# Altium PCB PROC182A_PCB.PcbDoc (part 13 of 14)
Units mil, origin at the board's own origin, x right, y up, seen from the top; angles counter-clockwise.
Board outline 3168.31 x 3700.79 mil, 8 copper layers (Top Layer, L2_GND1, L3_SIG1, L4_PWR1, L5_PWR2, L6_SIG2, L7_GND2, Bottom Layer), stack 58.1 mil thick; 580 components, 391 nets, 8314 pads, 4370 vias.
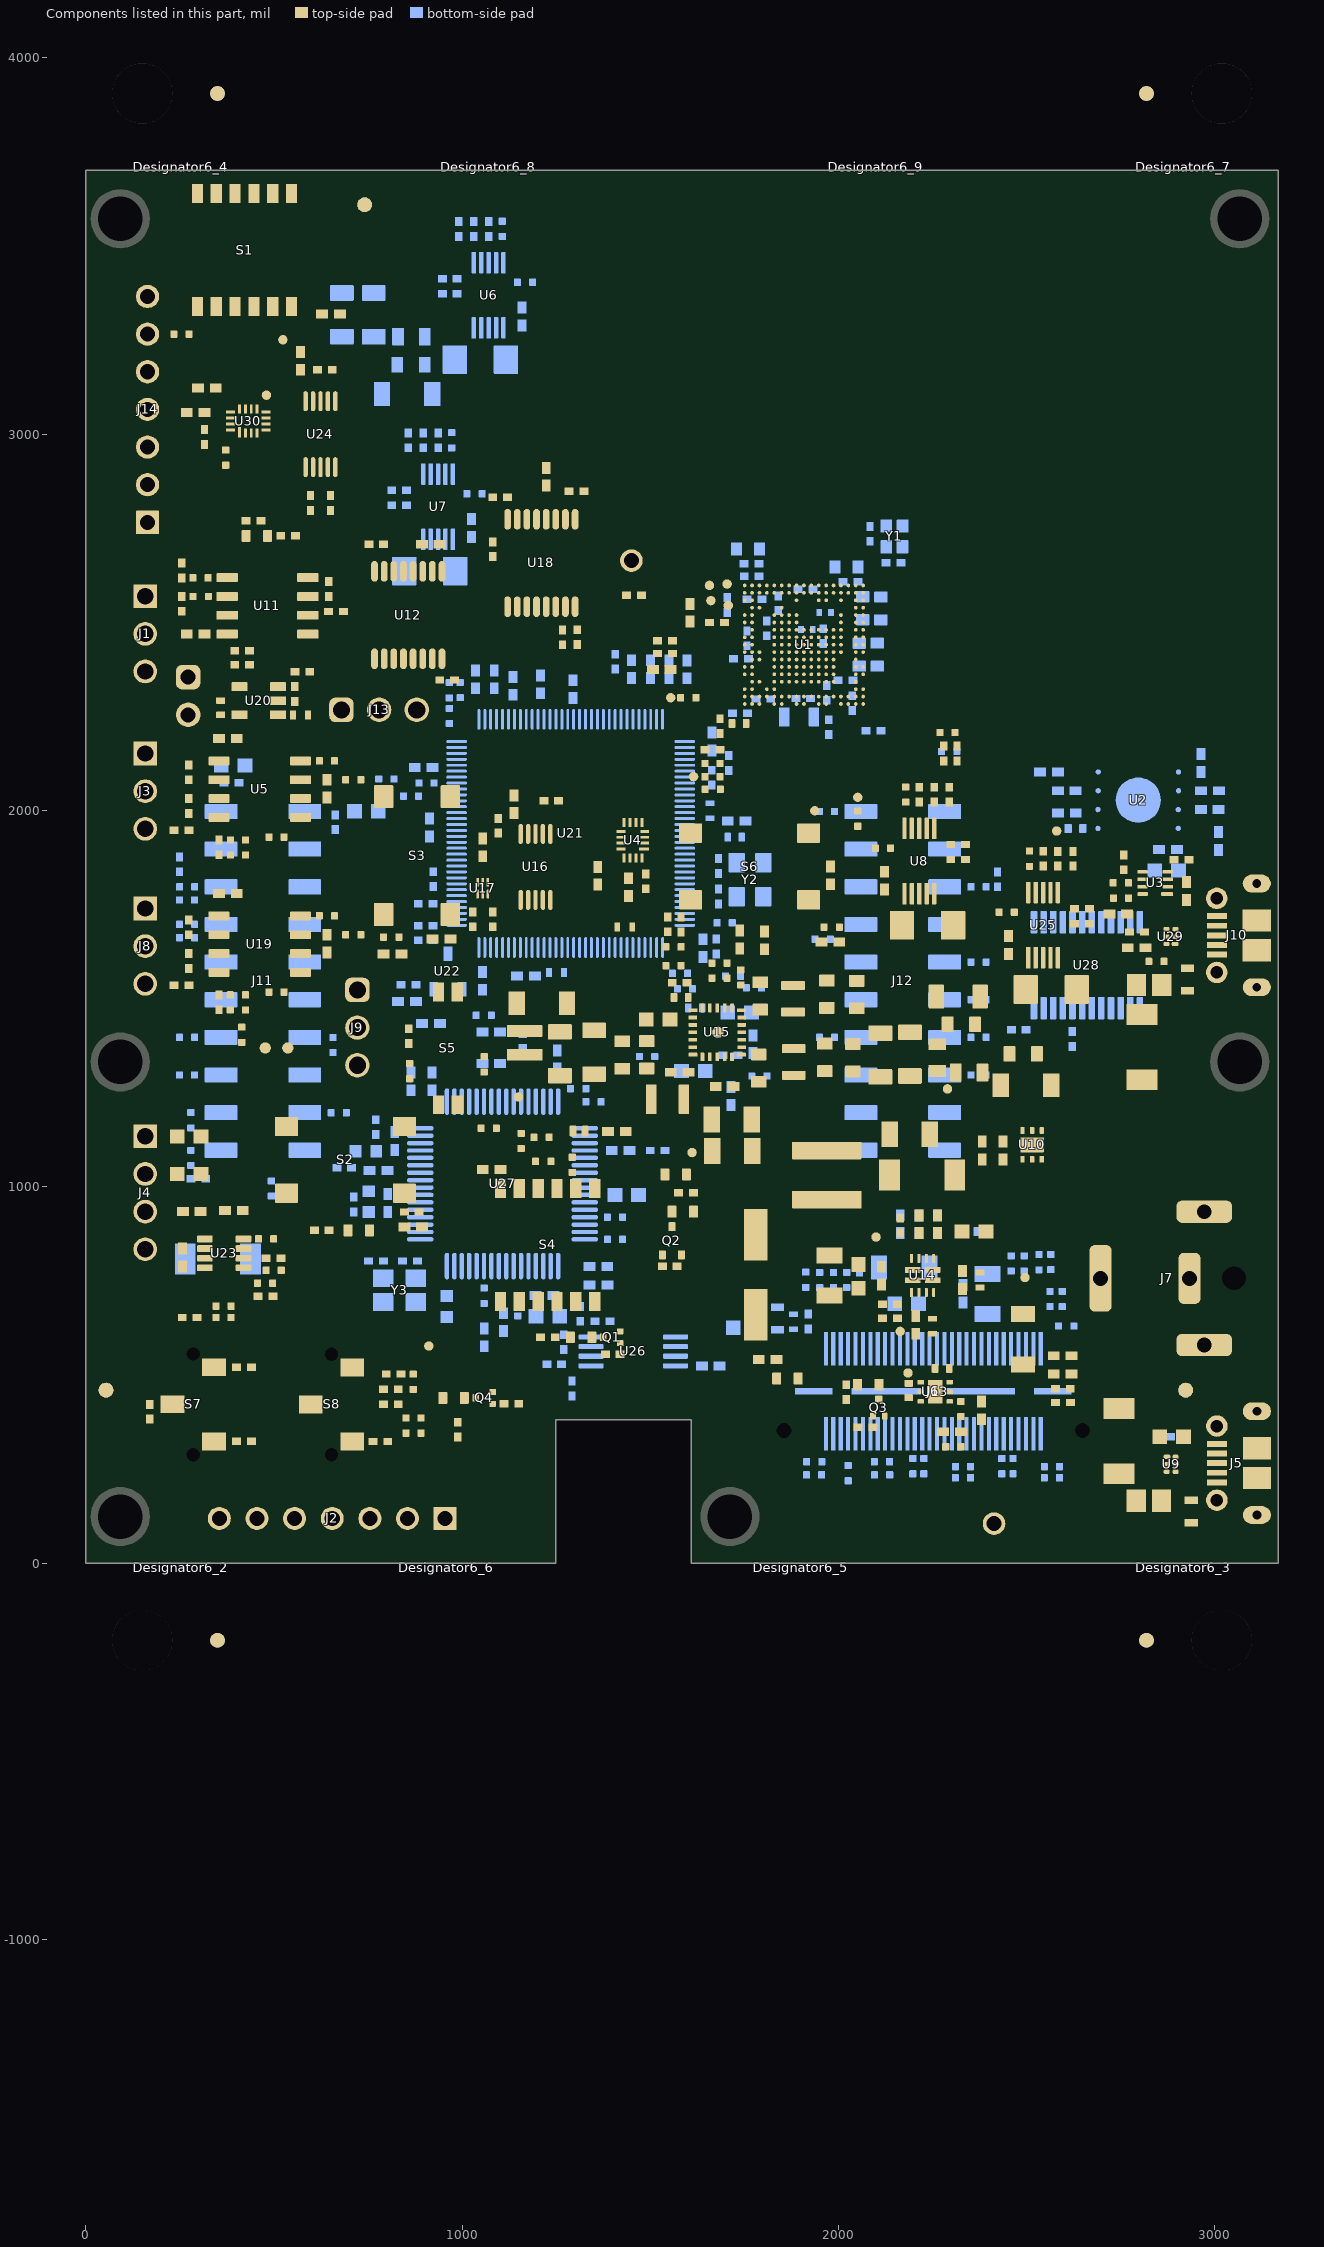
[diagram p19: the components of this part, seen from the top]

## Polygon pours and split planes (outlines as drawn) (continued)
GND on Top Layer "NONET_L08_P-001" (solid, remove dead copper, pour order 34): 1733.72,2617.8 2084.47,2617.8 2085.4,2616.88 2085.4,2262.73 1731.65,2262.73 1730.91,2263.47
VCC_3V3 on Top Layer "NONET_L08_P-001" (solid, remove dead copper, pour order 189): 1152.85,2008.86 1169.18,2025.19 1185.5,2025.19 1192.93,2017.76 1192.93,2008.23 1162.9,1978.2 1162.9,1911.54 1158.82,1907.46 1148.54,1907.46 1145.35,1913.04 1145.35,1949.34 1119.02,1975.67 1119.02,2001.9 1125.98,2008.86
REG_RF_1V2 on Top Layer "NONET_L08_P-001" (solid, remove dead copper, pour order 73): 17 vertices, not listed, extent 2339.79,1239 2669.94,1563.92
RADAR_1V_RF_OUT on Top Layer "NONET_L08_P-001" (solid, remove dead copper, pour order 28): 1995.61,2481.85 1995.61,2528.93 1998.45,2531.78 2024.25,2531.78 2027.3,2528.72 2027.3,2479.64 2022.1,2474.6 2002.85,2474.6
RADAR_1P2_RF on Top Layer "NONET_L08_P-001" (solid, remove dead copper, pour order 32): 1997.33,2409.91 2006.71,2400.54 2027.67,2400.54 2030.95,2403.82 2030.95,2463.69 2029.23,2465.41 1999.32,2465.41 1997.33,2463.42
RADAR_1V2 on Top Layer "RADAR_1V2_L01_P026" (solid, remove dead copper, pour order 26): 17 vertices, not listed, extent 1922.76,2337.22 1991.84,2445.69
GND on Top Layer "NONET_L08_P-001" (solid, remove dead copper, pour order 62): 1747.92,1061.38 1750.48,1058.81 1814.63,1058.81 1823.68,1067.87 1823.68,1215.56 1807.45,1231.8 1773,1231.8 1739.37,1265.43 1739.37,1280.1 1700.89,1280.1 1700.89,1256.2 1747.92,1209.17
GND on Top Layer "NONET_L08_P-001" (solid, remove dead copper, pour order 54): 1890.64,583.49 1754.41,583.49 1706.22,631.68 1706.22,756.41 1933.42,756.41 2125.59,756.41 2128.38,753.62 2128.38,678.62 2082.16,678.62 2073.69,670.15 1977.29,670.15
PMIC_OUT_1V2 on Top Layer "NONET_L08_P-001" (solid, remove dead copper, pour order 71): 1861.89,1341.34 2312.43,1341.34 2327.76,1326.01 2327.76,1217.8 2312.71,1202.76 1870.08,1202.76 1849.14,1223.7 1849.14,1327.78
NetD12_2 on Top Layer "NONET_L08_P-001" (solid, remove dead copper, pour order 83): 2817.41,1565.95 2817.41,1494.45 2823.39,1488.47 2844.84,1488.47 2850.8,1482.51 2850.8,1433.17 2845.79,1428.16 2845.08,1428.88 2743.06,1428.88 2736.55,1435.39 2736.55,1553.63 2748.87,1565.95
NetC43_1 on Top Layer "NONET_L08_P-001" (solid, remove dead copper, pour order 55): 2066.13,1051.27 2093.65,1023.74 2093.65,1003.21 2113.91,982.96 2177.27,982.96 2189.21,994.9 2189.01,995.1 2189.01,1152.68 2164.91,1176.78 1862.22,1176.78 1852.12,1166.68 1852.12,1074.81 1875.66,1051.27
PMIC_OUT_3V3 on Top Layer "NONET_L08_P-001" (solid, remove dead copper, pour order 64): 1249.02,1343.17 1219.99,1372.2 1122.13,1372.2 1117.97,1368.04 1117.97,1218.59 1123.7,1212.86 1466.07,1212.86 1491.95,1186.97 1511.46,1186.97 1532.55,1208.06 1532.55,1276.31 1518.74,1290.12 1518.74,1337.27 1512.84,1343.17
PMIC_OUT_3V3 on Top Layer "NONET_L08_P-001" (solid, remove dead copper, pour order 121): 1838.47,1358.49 1838.47,1333.37 1841.07,1330.78 1841.07,1317.54 1841.02,1317.5 1778.96,1317.5 1765.2,1331.26 1765.2,1353.36 1754.49,1364.07 1736.29,1364.07 1734.26,1366.11 1733.9,1375 1735.96,1377.06 1819.91,1377.06
NetD1_2 on Top Layer "NONET_L08_P-001" (solid, remove dead copper, pour order 201): 2702.22,264.81 2711.25,273.83 2792.64,273.83 2818.74,247.73 2818.74,135.31 2809.41,125.99 2784.94,125.99 2723.43,125.99 2702.22,147.19
GND on Top Layer "NONET_L08_P-001" (solid, remove dead copper, pour order 192): 2589.51,384.79 2589.51,561.42 2587.58,563.36 2471.82,563.36 2453.6,545.13 2453.6,461.63 2464.61,450.61 2464.61,383.67 2483.25,365.03 2569.75,365.03
5V_IN_USB on Top Layer "Top Layer-5V_IN_USB" (solid, remove dead copper, pour order 190): 40 vertices, not listed, extent 2229.27,355.87 2799.21,840.76
USB_5V on Top Layer "NONET_L08_P-001" (solid, remove dead copper, pour order 39): 2961.51,223.59 2948.6,210.68 2832.46,210.68 2832.46,133.67 2966.02,133.67 2975.2,142.85 2975.2,181.6 2999.98,206.39 3031.79,206.39 3031.79,223.59
GND on Top Layer "NONET_L08_P-001" (solid, remove dead copper, pour order 47): 24 vertices, not listed, extent 2898.32,50.42 3162.92,441.54
GND on Top Layer "NONET_L08_P-001" (solid, remove dead copper, pour order 60): 17 vertices, not listed, extent 2220.51,535.43 3084.96,1207.31
REG_1V2 on Top Layer "NONET_L08_P-001" (solid, remove dead copper, pour order 72): 2240.79,1362.56 2310,1362.56 2330.01,1382.57 2330.01,1628.76 2344.3,1643.62 2344.3,1727.44 2336.22,1735.52 2275.04,1735.52 2263.86,1724.34 2263.86,1722.31 2236.49,1694.93 2236.49,1366.86
RADAR_1P2_RF on Top Layer "NONET_L08_P-001" (solid, remove dead copper, pour order 104): 2419.65,1548.73 2419.65,1483.66 2424.23,1479.08 2524.82,1479.08 2533.5,1487.76 2533.5,1558.73 2529.3,1562.94 2433.85,1562.94
GND on Top Layer "NONET_L08_P-001" (solid, remove dead copper, pour order 75): 2502.81,1259.92 2526.42,1236.31 2608.19,1236.31 2608.19,1334.84 2579.85,1363.19 2567.47,1375.56 2507.45,1375.56 2502.81,1370.92
12V_DC_JACK on Top Layer "NONET_L08_P-001" (solid, remove dead copper, pour order 56): 2276.2,1089 2276.46,989.51 2528.87,989.51 2596.03,922.35 2656.74,861.63 2656.74,687.05 2675.25,668.53 2808.84,668.53 2813.66,673.35 2813.66,1038.7 2768.34,1084.02 2470.6,1084.02 2465.62,1089
PMIC_OUT_3V3 on Top Layer "NONET_L08_P-001" (solid, remove dead copper, pour order 119): 1838.47,1463.04 1838.47,1488.16 1841.07,1490.76 1841.07,1503.99 1841.02,1504.04 1778.96,1504.04 1765.2,1490.27 1765.2,1468.17 1754.49,1457.47 1736.29,1457.47 1734.26,1455.43 1733.9,1446.54 1735.96,1444.48 1819.91,1444.48
PMIC_VDD_1V8 on Top Layer "NONET_L08_P-001" (solid, remove dead copper, pour order 67): 1622.67,1435.37 1583.94,1435.37 1575.24,1444.08 1575.24,1457.98 1568.94,1464.27 1533.17,1464.27 1531.01,1462.11 1531.01,1425.66 1578.77,1425.66 1624.3,1425.66 1625.23,1426.58 1625.23,1434.32
PMIC_B1_SW on Top Layer "NONET_L08_P-001" (solid, remove dead copper, pour order 63): 19 vertices, not listed, extent 1572.81,1194.21 1644.24,1355.39
GND on Top Layer "NONET_L08_P-001" (solid, remove dead copper, pour order 66): 54 vertices, not listed, extent 1227.52,1360.11 1739.21,1542.99
PMIC_OUT_3V3 on Top Layer "NONET_L08_P-001" (solid, remove dead copper, pour order 181): 1678.06,1567.73 1675.03,1570.76 1655.14,1570.76 1644.05,1581.86 1629.2,1581.86 1624.59,1577.24 1624.59,1549.28 1630.5,1543.37 1675.32,1543.37 1678.06,1546.11
PMIC_LS_3V3 on Top Layer "NONET_L08_P-001" (solid, remove dead copper, pour order 68): 1600.59,1465.38 1589.61,1476.36 1589.61,1523.15 1581.89,1530.87 1581.89,1557.28 1588.83,1564.22 1611.91,1564.22 1616.94,1559.19 1616.94,1494.19 1624.03,1487.09 1624.03,1465.42 1621.94,1463.32 1602.59,1463.32
GND on Top Layer "NONET_L08_P-001" (solid, remove dead copper, pour order 45): 2221.57,1382.83 2221.57,1465.2 2182.37,1504.4 1940.22,1504.4 1940.22,1455.81 1902.81,1418.4 1731.86,1418.4 1730.99,1417.53 1731.52,1406.42 1759.1,1406.42 1764.94,1400.59 1905.56,1400.59 1946.44,1359.71 2198.44,1359.71
PMIC_B3_SW on Top Layer "NONET_L08_P-001" (solid, remove dead copper, pour order 44): 1850.93,1355.12 1911.93,1355.12 1913.03,1356.22 1913.03,1377.57 1894.25,1396.35 1729.89,1396.35 1729.89,1384.1 1821.94,1384.1
GND on Top Layer "NONET_L08_P-001" (solid, remove dead copper, pour order 120): 1832.54,1585.33 1818.38,1599.49 1784.3,1599.49 1768.42,1583.62 1768.42,1538.47 1777.33,1529.56 1817.5,1529.56 1832.54,1544.6
RADAR_1V2 on Top Layer "NONET_L08_P-001" (solid, remove dead copper, pour order 29): 1773.42,2524.66 1768.95,2529.13 1740.53,2529.13 1736.26,2533.39 1725.1,2533.39 1718.8,2527.09 1718.8,2513.49 1722.46,2509.84 1770.37,2509.84 1775.65,2515.12 1775.04,2515.72 1775.04,2522.02
GND on Top Layer "NONET_L08_P-001" (solid, remove dead copper, pour order 51): 18 vertices, not listed, extent 2246.64,627.84 2390.47,746.84
PMIC_OUT_3V3 on Top Layer "NONET_L08_P-001" (solid, remove dead copper, pour order 169): 558.17,2266.41 489.05,2266.41 487.51,2264.87 487.51,2224.83 507.77,2204.57 563.68,2204.57 568.8,2209.69 568.8,2255.78
GND on Top Layer "NONET_L08_P-001" (solid, remove dead copper, pour order 49): 20 vertices, not listed, extent 2167.69,406.05 2276.62,539.16
VCC_XDS_3V3 on Top Layer "NONET_L08_P-001" (solid, remove dead copper, pour order 50): 2225.94,487.46 2224.29,489.11 2169.78,489.11 2162.11,496.78 2162.11,506.13 2157.13,511.1 2140.86,511.1 2135.76,506 2135.76,470.13 2137.85,468.04 2221.51,468.04 2227.58,474.11 2227.58,485.21 2227.71,485.34
VCC_CAN_3V3 on Top Layer "NONET_L08_P-001" (solid, remove dead copper, pour order 65): 1216.35,1393.92 1216.35,1518.92 1209.9,1525.37 1101.74,1525.37 1091.98,1515.6 1091.98,1400.27 1098.32,1393.92
VBAT on Top Layer "NONET_L08_P-001" (solid, remove dead copper, pour order 148): 262.75,1053.2 249.96,1066 145.02,1066 126.57,1047.55 126.57,1021.46 145.02,1003.01 249.96,1003.01 262.75,1015.8
VSYS_IN on Top Layer "NONET_L08_P-001" (solid, remove dead copper, pour order 131): 262.75,1153.2 249.96,1166 126.57,1166 126.57,1103.01 249.96,1103.01 262.75,1115.8
GND on Top Layer "NONET_L08_P-001" (solid, remove dead copper, pour order 130): 1814.99,1298.62 1769.46,1298.62 1762.19,1291.35 1762.19,1248.66 1770.73,1240.12 1824.48,1240.12 1830.49,1246.13 1830.49,1292.93 1825.11,1298.3
PMIC_B2_SW on Top Layer "NONET_L08_P-001" (solid, remove dead copper, pour order 43): 1850.25,1478.87 1847.52,1476.15 1847.31,1462.58 1824.43,1439.69 1733.67,1439.69 1729.89,1435.92 1729.89,1426.84 1732.45,1424.28 1844.69,1424.28 1893.35,1424.28 1922.85,1453.78 1922.85,1474.75 1918.72,1478.87
VCC_3V3 on Top Layer "NONET_L08_P-001" (solid, remove dead copper, pour order 118): 2509.42,1637 2508.04,1635.61 2438.96,1635.61 2432.81,1629.46 2432.81,1586.01 2438.34,1580.48 2508.04,1580.48
GND on Top Layer "NONET_L08_P-001" (solid, remove dead copper, pour order 74): 2345.26,1574.59 2355.32,1584.65 2387.8,1584.65 2397.71,1574.73 2397.71,1417.04 2387.66,1406.99 2351.61,1406.99 2345.26,1413.34
VCC_3V3 on Top Layer "NONET_L08_P-001" (solid, remove dead copper, pour order 103): 2180.57,1807.24 2179.19,1805.86 2110.11,1805.86 2103.96,1799.71 2103.96,1756.25 2109.49,1750.73 2179.19,1750.73
RADAR_1V2 on Top Layer "NONET_L08_P-001" (solid, remove dead copper, pour order 102): 2120.81,1733.2 2200.82,1733.2 2202.79,1731.23 2202.79,1596.53 2189.87,1583.61 2125.13,1583.61 2112.42,1596.76 2112.42,1724.82
VCC_3V3 on Top Layer "NONET_L08_P-001" (solid, remove dead copper, pour order 101): 1570.19,1532.91 1570.19,1566.94 1567.12,1570.02 1511.86,1570.02 1506.52,1564.68 1506.52,1542.06 1515.68,1532.91 1546.57,1532.91
5V_IN_USB on Top Layer "NONET_L08_P-001" (solid, remove dead copper, pour order 97): 2676.86,1271.17 2696.77,1251.25 2848.83,1251.25 2854.86,1257.29 2854.86,1385.6 2850.69,1390.15 2696.58,1390.15 2676.86,1370.44
NetC158_1 on Top Layer "NONET_L08_P-001" (solid, remove dead copper, pour order 82): 2876.84,1651.72 2804.39,1651.72 2799.92,1647.26 2799.92,1588.82 2804.55,1584.2 2836.52,1584.2 2843.73,1591.4 2843.73,1603.61 2864.13,1624.01 2875.21,1624.01 2879.29,1628.09 2879.29,1650.33 2878.45,1651.17 2878.02,1651.17
GND on Top Layer "NONET_L08_P-001" (solid, remove dead copper, pour order 81): 22 vertices, not listed, extent 2910.24,1488.02 3151.9,1858.47
FTDI_VBUS on Top Layer "NONET_L08_P-001" (solid, remove dead copper, pour order 80): 20 vertices, not listed, extent 2833.04,1507.07 3031.5,1625.07
PMIC_OUT_1V8 on Top Layer "NONET_L08_P-001" (solid, remove dead copper, pour order 79): 1850.27,1586.47 1867.42,1603.62 2056.92,1603.62 2069.64,1590.91 2069.64,1522 2065.73,1518.09 1855.39,1518.09 1850.27,1523.21
PMIC_OUT_3V3 on Top Layer "NONET_L08_P-001" (solid, remove dead copper, pour order 70): 1632.84,1468.43 1634.85,1466.43 1641.88,1466.43 1645.04,1469.59 1645.04,1488.69 1649.91,1493.56 1649.91,1508.59 1648.49,1510.01 1625.69,1510.01 1625.69,1498.94 1632.84,1491.78
VCC_12V on Top Layer "NONET_L08_P-001" (solid, remove dead copper, pour order 52): 22 vertices, not listed, extent 1742.77,772.01 2218.5,1025.08
VSYS_IN on Top Layer "NONET_L08_P-001" (solid, remove dead copper, pour order 53): 2218.61,762.64 2219.21,762.05 2219.21,745.37 2219.28,745.29 2217.74,743.74 2179.94,743.74 2175.57,739.37 2175.57,730.17 2169.68,724.27 2145.07,724.27 2138.12,731.23 2138.12,755.09 2145.67,762.64
VSYS_IN on Top Layer "NONET_L08_P-001" (solid, remove dead copper, pour order 42): 2230.76,760.28 2292.3,760.28 2306.18,746.4 2306.18,721.51 2301.32,716.65 2270.22,716.65 2268.22,718.65 2268.22,736.09 2261.29,743.02 2230.76,743.02 2228.54,745.23 2228.56,745.25 2228.56,758.76
VCC_3V3 on L5_PWR2 "NONET_L08_P-001" (solid, remove dead copper, pour order 193): -0.98,3700.79 -0.98,0 1248.62,0 1248.62,381.95 1608.62,381.95 1608.62,0 3168.31,0 3168.31,3700.79
VSYS_IN on L5_PWR2 "NONET_L08_P-001" (solid, remove dead copper, pour order 175): 48 vertices, not listed, extent 111.48,544.4 2306.41,2005.19
PMIC_OUT_1V8 on L5_PWR2 "NONET_L08_P-001" (solid, remove dead copper, pour order 173): 25 vertices, not listed, extent 573.08,1567.61 2013.37,3317.42
RADAR_3V3 on L5_PWR2 "NONET_L08_P-001" (solid, remove dead copper, pour order 161): 25 vertices, not listed, extent 1522.64,2089.84 2276.56,2493.89
RADAR_1V8 on L5_PWR2 "NONET_L08_P-001" (solid, remove dead copper, pour order 183): 25 vertices, not listed, extent 1097.94,2250.71 2087.39,3228.16
5V_IN_USB on L5_PWR2 "NONET_L08_P-001" (solid, remove dead copper, pour order 153): 19 vertices, not listed, extent 2669.76,441.99 3110.74,1437.72
RADAR_1V2 on L5_PWR2 "NONET_L08_P-001" (solid, remove dead copper, pour order 160): 1867.62,2142.92 1834.71,2110.01 1834.71,1981.54 2036.04,1780.2 2036.04,1624.21 2070.03,1590.22 2215.77,1590.22 2215.77,1591.25 2295.06,1670.54 2295.06,1902.32 2054.47,2142.92
RADAR_1P2_RF on L5_PWR2 "NONET_L08_P-001" (solid, remove dead copper, pour order 171): 2645.25,1574.19 2645.25,1674.89 2654.78,1684.42 2654.78,2132.11 2499.36,2287.53 2223.67,2287.53 2223.67,2184.32 2393.7,2014.28 2393.7,1508.77 2413.84,1488.64 2559.69,1488.64
FTDI_3V3 on L5_PWR2 "NONET_L08_P-001" (solid, remove dead copper, pour order 154): 40 vertices, not listed, extent 671.87,1009.79 1349.47,1399.75
VCC_CAN_3V3 on L5_PWR2 "NONET_L08_P-001" (solid, remove dead copper, pour order 157): 34 vertices, not listed, extent 538.39,1462.24 1302.18,2128.37
GND on L6_SIG2 "NONET_L08_P-001" (solid, remove dead copper, pour order 205): -0.98,3700.79 -0.98,0 3168.31,0 3168.31,3700.79
RADAR_1P2_RF on L6_SIG2 "NONET_L08_P-001" (solid, remove dead copper, pour order 172): 1997.58,2409.91 2006.95,2400.54 2038.55,2400.54 2229.44,2209.65 2288.39,2209.65 2308.07,2229.33 2308.07,2399.61 2238.23,2469.45 2008.32,2468.2 1997.58,2457.46
VCC_3V3 on L6_SIG2 "NONET_L08_P-001" (solid, remove dead copper, pour order 182): 28 vertices, not listed, extent 2183.99,1803.15 2625,2173.23
GND on L2_GND1 "NONET_L08_P-001" (solid, remove dead copper, pour order 204): -0.98,3700.79 -0.98,0 3168.31,0 3168.31,3700.79
GND on L7_GND2 "NONET_L08_P-001" (solid, remove dead copper, pour order 99): -0.98,3700.79 -0.98,0 3168.31,0 3168.31,3700.79
GND on L3_SIG1 "NONET_L08_P-001" (solid, remove dead copper, pour order 98): -0.98,3700.79 -0.98,0 3168.31,0 3168.31,3700.79

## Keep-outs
Top Layer:
  lines w0.5: 1899.16,2503.07 1899.23,2503.07
Keep-Out Layer:
  circle w6: c1711.42,124.38 r118.11
  circle w6: c91.81,124.38 r118.11
  circle w1: c2648.08,352.53 r34
  circle w1: c1855.56,352.53 r35
  circle w6: c3065.87,1332.29 r118.11
  circle w6: c91.81,1332.29 r118.11
  circle w6: c3065.87,3572.29 r118.11
  circle w6: c91.81,3572.29 r118.11
  text ".Layer_Name" at 186.57,-874.24 h60

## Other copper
Top Layer:
  pour cut-out: 2065.55,2426.74 cw(c2065.55,2440.64) 2051.65,2440.64 cw(c2065.55,2440.64) 2065.55,2454.54 cw(c2065.55,2440.64) 2079.45,2440.64 cw(c2065.55,2440.64)
  pour cut-out: 2065.55,2466.11 cw(c2065.55,2480.01) 2051.65,2480.01 cw(c2065.55,2480.01) 2065.55,2493.91 cw(c2065.55,2480.01) 2079.45,2480.01 cw(c2065.55,2480.01)
  pour cut-out: 2065.55,2505.48 cw(c2065.55,2519.38) 2051.65,2519.38 cw(c2065.55,2519.38) 2065.55,2533.28 cw(c2065.55,2519.38) 2079.45,2519.38 cw(c2065.55,2519.38)
  pour cut-out: 2065.55,2544.85 cw(c2065.55,2558.75) 2051.65,2558.75 cw(c2065.55,2558.75) 2065.55,2572.65 cw(c2065.55,2558.75) 2079.45,2558.75 cw(c2065.55,2558.75)
  pour cut-out: 1947.44,2584.22 cw(c1947.44,2598.12) 1933.54,2598.12 cw(c1947.44,2598.12) 1947.44,2612.02 cw(c1947.44,2598.12) 1961.34,2598.12 cw(c1947.44,2598.12)
  pour cut-out: 1908.07,2584.22 cw(c1908.07,2598.12) 1894.17,2598.12 cw(c1908.07,2598.12) 1908.07,2612.02 cw(c1908.07,2598.12) 1921.97,2598.12 cw(c1908.07,2598.12)
  pour cut-out: 1829.33,2584.22 cw(c1829.33,2598.12) 1815.43,2598.12 cw(c1829.33,2598.12) 1829.33,2612.02 cw(c1829.33,2598.12) 1843.23,2598.12 cw(c1829.33,2598.12)
  pour cut-out: 1868.7,2584.22 cw(c1868.7,2598.12) 1854.8,2598.12 cw(c1868.7,2598.12) 1868.7,2612.02 cw(c1868.7,2598.12) 1882.6,2598.12 cw(c1868.7,2598.12)
  region net RX2: 1813.16,3076.92 1812.47,3076.69 1811.75,3076.49 1811.43,3076.42 1810.55,3076.25 1809.61,3076.12 1808.6,3076.04 1807.91,3076 1806.62,3075.97 1804.79,3075.97 1804.31,3075.97 1799.99,3075.97 1772.86,3075.97 1759.65,3068.34 1737.32,3068.34 1727.87,3073.8 1663.65,3073.8 1663.65,3082.19 1701.49,3082.19 1701.49,3096.24 1717.72,3096.24 1717.72,3082.19 1727.87,3082.19 1737.32,3087.64 1759.47,3087.64 1772.86,3079.91 1799.99,3079.91 1804.15,3079.91 1805.38,3079.9 1806.79,3079.91 1807.39,3079.92 1808.37,3079.97 1809.24,3080.04 1809.94,3080.14 1810.06,3080.16 1810.67,3080.28 1811.23,3080.43 1811.73,3080.59 1812.2,3080.78 1812.64,3081 1813.04,3081.25 1813.1,3081.29 1813.43,3081.55 1813.74,3081.83 1814.04,3082.13 1814.36,3082.47 1814.37,3082.46 1831.31,3099.4 1826.58,3104.14 1812.87,3090.43 1793.92,3109.38 1832.68,3148.14 1882.83,3097.99 1844.07,3059.23 1825.12,3078.18 1838.82,3091.89 1834.09,3096.62 1816.48,3079 1816.02,3078.58 1815.53,3078.19 1815.01,3077.83 1814.43,3077.49 1813.81,3077.19
  region net RX1: 1813.16,3176.92 1812.47,3176.69 1811.75,3176.49 1811.43,3176.42 1810.55,3176.25 1809.61,3176.12 1808.6,3176.04 1807.91,3176 1806.62,3175.97 1804.79,3175.97 1804.31,3175.97 1799.99,3175.97 1772.86,3175.97 1759.65,3168.34 1737.32,3168.34 1727.87,3173.8 1663.65,3173.8 1663.65,3182.19 1701.49,3182.19 1701.49,3196.24 1717.72,3196.24 1717.72,3182.19 1727.87,3182.19 1737.32,3187.64 1759.47,3187.64 1772.86,3179.91 1799.99,3179.91 1804.15,3179.91 1805.38,3179.9 1806.79,3179.91 1807.39,3179.92 1808.37,3179.97 1809.24,3180.04 1809.94,3180.14 1810.06,3180.16 1810.67,3180.28 1811.23,3180.43 1811.73,3180.59 1812.2,3180.78 1812.64,3181 1813.04,3181.25 1813.1,3181.29 1813.43,3181.55 1813.74,3181.83 1814.04,3182.13 1814.36,3182.47 1814.37,3182.46 1831.31,3199.4 1826.58,3204.14 1812.87,3190.43 1793.92,3209.38 1832.68,3248.14 1882.83,3197.99 1844.07,3159.23 1825.12,3178.18 1838.82,3191.89 1834.09,3196.62 1816.48,3179 1816.02,3178.58 1815.53,3178.19 1815.01,3177.83 1814.43,3177.49 1813.81,3177.19
  region net RX3: 1963.6,3130.46 1964.28,3130.69 1965.01,3130.89 1965.32,3130.96 1966.2,3131.12 1967.14,3131.25 1968.15,3131.34 1968.84,3131.38 1970.13,3131.41 1971.96,3131.41 1972.44,3131.4 1976.76,3131.4 2003.89,3131.4 2017.11,3139.03 2039.43,3139.03 2048.88,3133.57 2113.1,3133.57 2113.1,3125.19 2075.26,3125.19 2075.26,3111.13 2059.03,3111.13 2059.03,3125.19 2048.88,3125.19 2039.43,3119.73 2017.28,3119.73 2003.89,3127.46 1976.76,3127.46 1972.61,3127.46 1971.37,3127.47 1969.96,3127.47 1969.36,3127.46 1968.39,3127.41 1967.51,3127.33 1966.81,3127.23 1966.69,3127.22 1966.08,3127.09 1965.53,3126.95 1965.02,3126.78 1964.55,3126.59 1964.11,3126.37 1963.71,3126.12 1963.65,3126.08 1963.32,3125.83 1963.01,3125.55 1962.71,3125.24 1962.4,3124.91 1962.39,3124.92 1945.45,3107.97 1950.18,3103.24 1963.88,3116.94 1982.83,3097.99 1944.07,3059.23 1893.92,3109.38 1932.68,3148.14 1951.63,3129.19 1937.93,3115.49 1942.66,3110.76 1960.27,3128.38 1960.73,3128.8 1961.22,3129.19 1961.74,3129.54 1962.33,3129.88 1962.95,3130.19
  region net RX4: 1963.6,3230.46 1964.28,3230.69 1965.01,3230.89 1965.32,3230.96 1966.2,3231.12 1967.14,3231.25 1968.15,3231.34 1968.84,3231.38 1970.13,3231.41 1971.96,3231.41 1972.44,3231.4 1976.76,3231.4 2003.89,3231.4 2017.11,3239.03 2039.43,3239.03 2048.88,3233.57 2113.1,3233.57 2113.1,3225.19 2075.26,3225.19 2075.26,3211.13 2059.03,3211.13 2059.03,3225.19 2048.88,3225.19 2039.43,3219.73 2017.28,3219.73 2003.89,3227.46 1976.76,3227.46 1972.61,3227.46 1971.37,3227.47 1969.96,3227.47 1969.36,3227.46 1968.39,3227.41 1967.51,3227.33 1966.81,3227.23 1966.69,3227.22 1966.08,3227.09 1965.53,3226.95 1965.02,3226.78 1964.55,3226.59 1964.11,3226.37 1963.71,3226.12 1963.65,3226.08 1963.32,3225.83 1963.01,3225.55 1962.71,3225.24 1962.4,3224.91 1962.39,3224.92 1945.45,3207.97 1950.18,3203.24 1963.88,3216.94 1982.83,3197.99 1944.07,3159.23 1893.92,3209.38 1932.68,3248.14 1951.63,3229.19 1937.93,3215.49 1942.66,3210.76 1960.27,3228.38 1960.73,3228.8 1961.22,3229.19 1961.74,3229.54 1962.33,3229.88 1962.95,3230.19
  pour cut-out: 1652.5,3086.12 1652.5,3069.86 1691.26,3069.86 1691.26,3054.11 1766.32,3054.11 1766.32,3037.28 2010.43,3037.28 2010.43,3105.5 2085.49,3105.5 2085.49,3121.25 2124.25,3121.25 2124.25,3137.51 2085.49,3137.51 2085.49,3153.26 2010.43,3153.26 2010.43,3205.5 2085.49,3205.5 2085.49,3221.25 2124.25,3221.25 2124.25,3237.51 2085.49,3237.51 2085.49,3253.26 2010.4,3253.26 2010.4,3270.09 1766.32,3270.09 1766.32,3201.88 1691.26,3201.88 1691.26,3186.12 1652.5,3186.12 1652.5,3169.86 1691.26,3169.86 1691.26,3154.11 1766.32,3154.11 1766.32,3101.88 1691.26,3101.88 1691.26,3086.12
  region net TX1: 2954.06,2892.95 2954.29,2893.64 2954.49,2894.36 2954.57,2894.68 2954.73,2895.55 2954.86,2896.49 2954.95,2897.5 2954.98,2898.19 2955.02,2899.48 2955.01,2901.31 2955.01,2901.79 2955.01,2906.12 2955.01,2933.24 2962.64,2946.46 2962.64,2968.78 2957.18,2978.23 2957.18,3042.46 2948.8,3042.46 2948.8,3004.61 2934.74,3004.61 2934.74,2988.38 2948.8,2988.38 2948.8,2978.23 2943.34,2968.78 2943.34,2946.64 2951.07,2933.24 2951.07,2906.12 2951.07,2901.96 2951.08,2900.73 2951.08,2899.31 2951.06,2898.72 2951.02,2897.74 2950.94,2896.86 2950.84,2896.16 2950.82,2896.05 2950.7,2895.43 2950.56,2894.88 2950.39,2894.37 2950.2,2893.9 2949.98,2893.47 2949.73,2893.06 2949.69,2893 2949.44,2892.67 2949.16,2892.36 2948.85,2892.06 2948.52,2891.75 2948.52,2891.74 2931.58,2874.8 2926.85,2879.53 2940.55,2893.23 2921.6,2912.18 2882.84,2873.43 2932.99,2823.28 2971.75,2862.03 2952.8,2880.98 2939.1,2867.28 2934.36,2872.01 2951.98,2889.62 2952.41,2890.09 2952.79,2890.58 2953.15,2891.1 2953.49,2891.68 2953.79,2892.3
  pour cut-out: 2909.73,2481.86 2893.47,2481.86 2893.47,2520.61 2877.72,2520.61 2877.72,2595.68 2725.48,2595.68 2725.48,2520.61 2709.73,2520.61 2709.73,2481.86 2693.47,2481.86 2693.47,2520.61 2677.72,2520.61 2677.72,2595.78 2660.75,2595.78 2660.74,2595.79 2660.89,2595.94 2660.89,2939.78 2729.11,2939.78 2729.11,3014.85 2744.86,3014.85 2744.86,3053.6 2761.12,3053.6 2761.12,3014.85 2776.87,3014.85 2776.87,2939.78 2929.11,2939.78 2929.11,3014.85 2944.86,3014.85 2944.86,3053.6 2961.12,3053.6 2961.12,3014.85 2976.87,3014.85 2976.87,2939.78 2993.7,2939.78 2993.7,2595.68 2925.48,2595.68 2925.48,2520.61 2909.73,2520.61
  region net TX2: 2754.06,2892.95 2754.29,2893.64 2754.49,2894.36 2754.57,2894.68 2754.73,2895.55 2754.86,2896.49 2754.95,2897.5 2754.98,2898.19 2755.02,2899.48 2755.01,2901.31 2755.01,2901.79 2755.01,2906.12 2755.01,2933.24 2762.64,2946.46 2762.64,2968.78 2757.18,2978.23 2757.18,3042.46 2748.8,3042.46 2748.8,3004.61 2734.74,3004.61 2734.74,2988.38 2748.8,2988.38 2748.8,2978.23 2743.34,2968.78 2743.34,2946.64 2751.07,2933.24 2751.07,2906.12 2751.07,2901.96 2751.08,2900.73 2751.08,2899.31 2751.06,2898.72 2751.02,2897.74 2750.94,2896.86 2750.84,2896.16 2750.82,2896.05 2750.7,2895.43 2750.56,2894.88 2750.39,2894.37 2750.2,2893.9 2749.98,2893.47 2749.73,2893.06 2749.69,2893 2749.44,2892.67 2749.16,2892.36 2748.85,2892.06 2748.52,2891.75 2748.52,2891.74 2731.58,2874.8 2726.85,2879.53 2740.55,2893.23 2721.6,2912.18 2682.84,2873.43 2732.99,2823.28 2771.75,2862.03 2752.8,2880.98 2739.1,2867.28 2734.36,2872.01 2751.98,2889.62 2752.41,2890.09 2752.79,2890.58 2753.15,2891.1 2753.49,2891.68 2753.79,2892.3
  region net TX3: 2700.53,2642.51 2700.3,2641.82 2700.1,2641.1 2700.02,2640.78 2699.86,2639.91 2699.73,2638.97 2699.64,2637.95 2699.61,2637.27 2699.57,2635.97 2699.58,2634.15 2699.58,2633.67 2699.58,2629.34 2699.58,2602.21 2691.95,2589 2691.95,2566.68 2697.41,2557.23 2697.41,2493 2705.79,2493 2705.79,2530.85 2719.85,2530.85 2719.85,2547.08 2705.79,2547.08 2705.79,2557.23 2711.25,2566.68 2711.25,2588.82 2703.52,2602.21 2703.52,2629.34 2703.52,2633.5 2703.51,2634.73 2703.51,2636.14 2703.53,2636.74 2703.57,2637.72 2703.65,2638.6 2703.75,2639.3 2703.77,2639.41 2703.89,2640.03 2704.03,2640.58 2704.2,2641.09 2704.39,2641.56 2704.61,2641.99 2704.86,2642.4 2704.9,2642.45 2705.15,2642.79 2705.43,2643.1 2705.74,2643.4 2706.07,2643.71 2706.07,2643.72 2723.01,2660.66 2727.74,2655.93 2714.04,2642.23 2732.99,2623.28 2771.75,2662.03 2721.6,2712.18 2682.84,2673.43 2701.79,2654.48 2715.49,2668.18 2720.23,2663.44 2702.61,2645.84 2702.18,2645.37 2701.8,2644.88 2701.44,2644.36 2701.1,2643.78 2700.8,2643.16
  region net TX4: 2900.53,2642.51 2900.3,2641.82 2900.1,2641.1 2900.02,2640.78 2899.86,2639.91 2899.73,2638.97 2899.64,2637.95 2899.61,2637.27 2899.57,2635.97 2899.58,2634.15 2899.58,2633.67 2899.58,2629.34 2899.58,2602.21 2891.95,2589 2891.95,2566.68 2897.41,2557.23 2897.41,2493 2905.79,2493 2905.79,2530.85 2919.85,2530.85 2919.85,2547.08 2905.79,2547.08 2905.79,2557.23 2911.25,2566.68 2911.25,2588.82 2903.52,2602.21 2903.52,2629.34 2903.52,2633.5 2903.51,2634.73 2903.51,2636.14 2903.53,2636.74 2903.57,2637.72 2903.65,2638.6 2903.75,2639.3 2903.77,2639.41 2903.89,2640.03 2904.03,2640.58 2904.2,2641.09 2904.39,2641.56 2904.61,2641.99 2904.86,2642.4 2904.9,2642.45 2905.15,2642.79 2905.43,2643.1 2905.74,2643.4 2906.07,2643.71 2906.07,2643.72 2923.01,2660.66 2927.74,2655.93 2914.04,2642.23 2932.99,2623.28 2971.75,2662.03 2921.6,2712.18 2882.84,2673.43 2901.79,2654.48 2915.49,2668.18 2920.23,2663.44 2902.61,2645.84 2902.18,2645.37 2901.8,2644.88 2901.44,2644.36 2901.1,2643.78 2900.8,2643.16
  text ".Layer_Name" at 186.57,-874.24 h60
L2_GND1:
  text ".Layer_Name" at 186.57,-874.24 h60
L3_SIG1:
  text ".Layer_Name" at 186.57,-874.24 h60
L5_PWR2:
  text ".Layer_Name" at 186.57,-874.24 h60
L7_GND2:
  text ".Layer_Name" at 383.42,-283.69 h60
L4_PWR1:
  text ".Layer_Name" at 186.57,-874.24 h60
L6_SIG2:
  text ".Layer_Name" at 186.57,-874.24 h60
Bottom Layer:
  pour cut-out: 2174.94,2551.18 2177.47,2553.71 2177.43,2554.6 2177.43,2622.66 2163.1,2636.99 2068.61,2636.99 2068.61,2666.34 2038.61,2666.34 2031.65,2659.37 2031.65,2588.92 2006.77,2564.05 2006.77,2572.6 2023.84,2589.66 2023.84,2664.94 2028.83,2669.93 2073.5,2669.93 2073.5,2647.64 2080.07,2641.08 2167.95,2641.08 2184.54,2624.48 2184.54,2551.18 2178.84,2545.48 2149.02,2545.48 2137.96,2534.43 2137.67,2534.43 2133.26,2538.84 2145.6,2551.18
  pour cut-out: 2098.28,2640.98 2098.28,2604.41 2084.97,2591.1 2035.09,2591.1 2034.08,2590.09 2034.08,2588.67 2034.95,2587.8 2036.58,2589.44 2089.93,2589.44 2102.07,2601.57 2102.07,2640.89
  text ".Layer_Name" at 186.57,-874.24 h60

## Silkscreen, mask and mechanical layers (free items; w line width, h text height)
Top Overlay:
  drawing of 118 lines, arcs and shapes, not listed
  text "PROC182" at 838.99,3325.43 h25
  text "REV A" at 1025.55,3325.43 h25
  text "PMIC 1V8" at 327.03,3225.71 h25
  text "HOST_CLK_REQ" at 272.78,3169.94 h22
  text "SPIB_CONN" at 240.72,2795.84 h25 r90
  text "RESET_OUT" at 377.02,2681.15 h22
  text "GPADC3" at 1593.19,2627.75 h22
  text "SCL" at 122.38,2625.38 h22
  text "1V_RF_OUT" at 1401.34,2625.51 h25 r90
  text "GPADC4" at 1545.85,2616.87 h22 r90
  text "I2C CONN" at 224.15,2532.15 h22 r90
  text "GPADC1" at 1398.04,2526.11 h22
  text "GPADC2" at 1568.17,2468.29 h22 r90
  text "SDA" at 224.15,2431.38 h22 r90
  text "RX" at 763,2334.44 h25
  text "GND" at 844.13,2333.93 h25
  text "TX" at 657.58,2332.38 h25
  text "R" at 1266.37,2305.45 h6.21
  text "R" at 1266.37,2305.45 h6.21
  text "GND" at 113.86,2301.84 h22
  text "RTC_CLK_IN" at 1302.72,2266.69 h25
  text "CAN_FD_L" at 19.8,2227 h20
  text "MISTRAL" at 1054.72,2216.16 h56.97
  text "VPP_1P7" at 211.49,2200.6 h22 r90
  text "UARTB_CONN" at 740.47,2184.52 h25
  text "USER_SWITCH_1" at 757.94,2088.88 h25
  text "WU_REQ" at 1556.01,2073.37 h25 r90
  text "GND" at 216.47,2022.7 h22 r90
  text "LVDS_VALID" at 2096.64,2012.01 h25 r90
  text "VCC_3V3" at 2514.53,2004.15 h22
  text "OSC_CLKOUT" at 1915.99,1993.82 h25 r90
  text "USER_SWITCH_2" at 1583.52,1984.33 h22
  text "CAN_FD_CONN" at 249.88,1961.39 h22 r90
  text "CAN_FD_H" at 15.67,1866.76 h20
  text "CAN_FD_B_L" at 18.43,1813.35 h20
  text "GND" at 212.47,1610.09 h20 r90
  text "CAN_FD_B_CONN" at 247.54,1563.41 h22 r90
  text "XDS_I2C_SW" at 853.79,1553.81 h22
  text "TX" at 808.01,1503.8 h25 r90
  text "CAN_FD_B_H" at 22.83,1456.5 h20
  text "FTDI_USB" at 2946.09,1455.46 h25
  text "RX" at 812.55,1405.24 h25 r90
  text "UARTA" at 650.65,1305.18 h25 r90
  text "H/W TRG" at 602.37,1297.38 h25 r90
  text "GND" at 814.37,1288.52 h25 r90
  text "RESET SWITCH" at 535.35,1217.91 h25
  text "PMIC_3V3" at 1046.96,1207.41 h25
  text "PMIC_1V2" at 2125.02,1197.65 h25
  text "VSYS_IN" at 125.1,1191.91 h20
  text "VSYS" at 1495.54,1083.08 h25
  text "FTDI" at 1624,1022 h22
  text "DC 12V/5V" at 2905.15,1020.07 h25
  text "SUSPEND" at 1669,990 h22
  text "VBAT" at 193.5,974.7 h20
  text "PGOOD" at 1635.68,925.46 h20
  text "LIN_BUS" at 190.02,880.81 h20
  text "VCC_12V" at 1914.66,876.77 h25
  text "nERROR OUT LED" at 689.31,793.96 h20
  text "5V_USB" at 2474.06,780.07 h25
  text "GND" at 123.94,770.71 h20
  text "LIN_CONN" at 29.33,706.06 h25
  text "SOP0_H" at 123.18,606.51 h22
  text "FUNCTIONAL" at 327.23,602.9 h22
  text "VOUT_STS" at 1975.79,573.72 h22
  text "PMIC_CLK_O" at 929.95,567.4 h20
  text "MODE" at 378.58,564.14 h22
  text "XDS_3V3" at 2234.32,557.86 h22
  text "SOP1_H" at 739.99,553.97 h22
  text "USER_LED_2" at 1888.02,538.15 h22
  text "USER LED 1" at 932.92,508.57 h22
  text "RESET_LED" at 1192.98,509.15 h25
  text "VSYS" at 1733.35,479.08 h22
  text "XDS_USB" at 2982,446.17 h25
  text "SOP1_L" at 737.84,262.7 h22
  text "FLASHING" at 322.32,222.35 h22
  text "SOP0_L" at 131.02,216.15 h22
  text "MODE" at 361.43,187.87 h22
  text "GND" at 2455.84,80.85 h25
  text "SPI_A_HEADER" at 540.71,30.79 h25
  text ".Layer_Name" at 186.57,-874.24 h60
Bottom Overlay:
  circle w10: c894.02,650.09 r4.76
  circle w11.62: c1966.54,632.87 r2.78
  rectangle: 1469.04,3266.83 2157.48,3365.06
  lines w6: 1623.03,3073.15 ccw(c1643.03,3073.15) 1643.03,3053.15 2262.48,3053.15 ccw(c2262.48,3073.15) 2282.48,3073.15 2282.48,3188.66 ccw(c2262.48,3188.66) 2262.48,3208.66 1643.03,3208.66 ccw(c1643.03,3188.66) 1623.03,3188.66 1623.03,3073.15
  lines w10: 1469.04,3266.97 2295.23,3266.97 2295.23,3367.11 ; 1469.04,3366.97 2295.23,3366.97 ; 1469.59,3266.97 1469.59,3366.97 ; 2157.48,3266.83 2157.48,3365.06
  text "SL#" at 2275.53,3298.26 h70
  text "FY23-24/02016000101" at 2227.3,2967.58 h25
  text "SPIB_CONN" at 246.03,2866.45 h25 r270
  text "I2C CONN" at 258.57,2461.07 h22 r270
  text "For evaluation only; not FCC approved for resale." at 3044.43,2343.99 h45.3 r270
  text "LP/BP CONN" at 710.6,2101.25 h25
  text "LP/BP CONN" at 2415.28,2070.07 h25
  text "5V" at 697.94,2040.15 h60
  text "3V3" at 299.85,2007.75 h60
  text "GND" at 2457.2,1978.52 h60
  text "CAN_FD_CONN" at 70.52,1940.17 h22 r270
  text "CAN_FD_B_CONN" at 72.79,1515.58 h22 r270
  text "LIN_CONN" at 68.27,880 h25 r270
  text "DCA1000_CONN" at 2713.1,331.37 h25 r270
  text "SPI_A_HEADER" at 802.2,189.64 h25
  text "GND" at 2445.8,41.4 h25
  text ".Layer_Name" at 186.57,-874.24 h60
Top Paste:
  text ".Layer_Name" at 186.57,-874.24 h60
Bottom Paste:
  text ".Layer_Name" at 186.57,-874.24 h60
Top Solder:
  region: 2428.66,2160.43 2183.74,2405.36 2095.42,2405.36 2080.83,2419.95 2080.83,2591.25 2086.32,2596.44 2165.64,2596.44 2174.25,2605.04 2174.25,2625.84 2161.77,2638.32 2120.33,2638.32 2120.33,2666.17 2078.74,2707.76 2058.47,2707.76 2048.64,2697.93 2048.64,2684.5 2007.89,2643.75 2007.89,2618.68 2002.15,2612.94 1787.3,2612.94 1724.47,2675.77 1626.4,2675.76 1512.44,2789.73 1424.84,2789.73 1417.24,2797.33 1417.24,3700.74 3168.31,3700.74 3168.31,2160.43
  region: 2083.62,2446.14 2083.61,2435.05 2076.55,2435.05 2076.55,2446.14
  region: 2083.62,2485.51 2083.61,2474.42 2076.55,2474.42 2076.55,2485.51
  region: 2083.62,2524.88 2083.61,2513.79 2076.55,2513.79 2076.55,2524.88
  region: 2083.62,2564.25 2083.61,2553.16 2076.55,2553.16 2076.55,2564.25
  region: 1941.94,2616.18 1953.03,2616.18 1953.03,2609.11 1941.94,2609.11
  region: 1902.57,2616.18 1913.66,2616.18 1913.66,2609.11 1902.57,2609.11
  region: 1863.2,2616.18 1874.29,2616.18 1874.29,2609.11 1863.2,2609.11
  region: 1823.83,2616.18 1834.92,2616.18 1834.92,2609.11 1823.83,2609.11
  text ".Layer_Name" at 186.57,-874.24 h60
  text ".Layer_Name" at 186.57,-874.24 h60
Bottom Solder:
  region: 1830.4,2450.48 1839.27,2459.35 1902.77,2459.35 1913.39,2448.73 1913.39,2353.59 1904.34,2344.54 1836.76,2344.54 1830.4,2350.9
  text ".Layer_Name" at 186.57,-874.24 h60
Drill Guide:
  text ".Layer_Name" at 186.57,-874.24 h60
M1 Board Outline:
  lines w5: 117.12,-78.74 0,-78.74 0,-354.34 2479.33,-354.34 3168.31,-354.34 3168.31,-78.74 ; 387.99,-78.74 564.69,-78.74 ; 822.26,-78.74 564.69,-78.74 ; 1081.32,-78.74 1223.13,-78.74 ; 2034.98,-78.74 2216.05,-78.74 ; 3051.19,-78.74 3168.31,-78.74 ; 564.69,-78.74 564.69,-78.74 ; 1223.13,-78.74 1223.13,-78.74 ; 1223.13,-78.74 1327.36,-78.74 ; 1327.36,-78.74 1327.36,-78.74 ; 1327.36,-78.74 1327.36,0 1327.36,303.21 1529.88,303.21 1529.88,0 1529.88,-78.74 1634.12,-78.74 1764.12,-78.74 ; 1764.12,-78.74 1764.12,-78.74 ; 2216.05,-78.74 2216.05,-78.74 ; 2216.05,-78.74 2332.75,-78.74 ; 2332.75,-78.74 2603.62,-78.74 2780.32,-78.74 ; 2332.75,-78.74 2332.75,-78.74 ; 2780.32,-78.74 2780.32,-78.74 ; 3168.31,-78.74 3168.31,-78.74 ; 0,0 1248.62,0 1248.62,381.95 1608.62,381.95 1608.62,0 3168.31,0 3168.31,3700.79 0,3700.79 0,0 ; 0,3779.53 688.98,3779.53 3168.31,3779.53 3168.31,4055.13 688.98,4055.13 0,4055.13 0,3779.53
  text ".Layer_Name" at 179.96,-797.55 h40
M2 Board Dimensions:
  text ".Layer_Name" at 174.69,-872.3 h60
M3 3D STEP Top:
  text ".Layer_Name" at 186.57,-874.24 h60
M4 3D STEP Bottom:
  text ".Layer_Name" at 186.57,-874.24 h60
M5 Assembly Top:
  lines w10: -682.43,-945.91 5917.57,-945.91 ; -682.43,-742.58 5919.57,-742.58 ; -682.43,-539.25 -682.43,-1149.25 3322.57,-1149.25 5919.57,-1149.25 5919.57,-539.25 -681.93,-539.25 -681.93,-1149.25 893.57,-1149.25 ; 1782.57,-1149.25 1782.57,-539.25 ; 3049.57,-742.58 3049.57,-539.25 ; 3889.57,-742.58 3889.57,-539.25 ; 4511.57,-1155.75 4511.57,-952.91
  text "COMPONENTS MARKED 'DNP' SHOULD NOT BE POPULATED." at 39.82,4288.04 h60
  text "ASSEMBLY VARIANT:" at 39.32,4172.54 h60
  text ".VariantName" at 1075.32,4172.54 h60
  text "PCB VIEWED FROM TOP SIDE" at -618.93,-671.41 h60
  text "BOARD #:" at 1857.57,-671.41 h60
  text ".PRJ_Number" at 2403.07,-671.41 h60
  text "REV:" at 3247.57,-671.41 h60
  text ".PCB_Rev" at 3539.07,-671.41 h60
  text "SVN REV:" at 4085.57,-671.41 h60
  text ".VersionControl_RevNumber" at 4591.57,-671.41 h60
  text "Assembly Layer Top" at 176.57,-870.75 h60
  text "TID #:" at 1857.57,-874.75 h60
  text ".TID" at 2403.07,-874.75 h60
  text "PLOT NAME =" at -618.93,-1080.08 h60
  text ".plot_File_Name" at 186.57,-1080.08 h60
  text "GENERATED    :" at 1859.57,-1080.08 h60
  text ".Print_Date" at 2729.07,-1080.08 h60
  text ".Print_Time" at 3458.07,-1080.08 h60
  text "TEXAS INSTRUMENTS" at 4722.57,-1080.08 h60
M6 Assembly Bottom:
  lines w5: 1577.2,3051.31 ccw(c1602.2,3051.31) 1602.2,3026.31 2202.2,3026.31 ccw(c2202.2,3051.31) 2227.2,3051.31 2227.2,3201.31 ccw(c2202.2,3201.31) 2202.2,3226.31 1602.2,3226.31 ccw(c1602.2,3201.31) 1577.2,3201.31 1577.2,3051.31
  lines w10: -682.93,-743.08 5919.07,-743.08 ; -680.93,-946.41 5919.07,-946.41 ; 725.07,-1156.25 725.07,-953.41 ; 1347.07,-743.08 1347.07,-539.75 ; 2187.07,-743.08 2187.07,-539.75 ; 3454.07,-1149.75 3454.07,-539.75 ; 4343.07,-1149.75 5918.57,-1149.75 5918.57,-539.75 -682.93,-539.75 -682.93,-1149.75 1914.07,-1149.75 5919.07,-1149.75 5919.07,-539.75
  text ".Designator" at 2131.16,3110.16 h40
  text "COMPONENTS MARKED 'DNP' SHOULD NOT BE POPULATED." at 5916.15,-316.7 h60
  text ".VariantName" at 4872.15,-432.7 h60
  text "ASSEMBLY VARIANT:" at 5911.15,-432.7 h60
  text ".VersionControl_RevNumber" at 645.07,-671.91 h60
  text "SVN REV:" at 1151.07,-671.91 h60
  text ".PCB_Rev" at 1697.57,-671.91 h60
  text "REV:" at 1989.07,-671.91 h60
  text ".PRJ_Number" at 2833.57,-671.91 h60
  text "BOARD #:" at 3379.07,-671.91 h60
  text "PCB VIEWED FROM BOTTOM SIDE" at 5855.57,-671.91 h60
  text "Assembly Bottom Layer" at 5494.57,-860.75 h60
  text ".TID" at 2833.57,-875.25 h60
  text "TID #:" at 3379.07,-875.25 h60
  text "TEXAS INSTRUMENTS" at 514.07,-1080.58 h60
  text ".Print_Time" at 1778.57,-1080.58 h60
  text ".Print_Date" at 2507.57,-1080.58 h60
  text "GENERATED    :" at 3377.07,-1080.58 h60
  text ".plot_File_Name" at 5050.07,-1080.58 h60
  text "PLOT NAME =" at 5855.57,-1080.58 h60
M7 LPKF Text Top:
  lines w2: 1814.29,2787.96 1845.77,2787.96 ; 1822.16,2787.96 1837.9,2787.96 ; 1830.03,2772.22 1830.03,2803.7 ; 1830.03,2780.09 1830.03,2795.83
M10 Fab Notes:
  drawing of 251 lines, arcs and shapes, not listed
  text "1" at 349.4,8020.75 h70
  text "2" at 2845.07,8020.75 h70
  text "3" at 5334.41,8020.75 h70
  text "4" at 7841.08,8020.75 h70
  text "5" at 10340.07,8020.75 h70
  text "6" at 12845.07,8020.75 h70
  text "A" at -806.93,6877.75 h70
  text "A" at 13993.07,6877.75 h70
  text "DESIGN INFORMATION" at 11991.59,6340.43 h60
  text "4.8" at 12386.06,6211.03 h60
  text "MIN. TRACK WIDTH:" at 11347.03,6208.3 h60
  text "MIL" at 12598.03,6208.3 h60
  text "3.9" at 12383.52,6091.65 h60
  text "MIN. CLEARANCE:" at 11347.03,6084.17 h60
  text "MIL" at 12598.03,6084.17 h60
  text "MIN. VIA PAD SIZE:" at 11347.03,5960.05 h60
  text "13.77" at 12288.41,5958.58 h60
  text "MIL" at 12620.57,5951.25 h60
  text "EXTERNAL" at 12868.17,5832.74 h60
  text "0.127mm (5.0MIL)" at 12042.03,5830.15 h60
  text "MINIMUM ANNULAR RING" at 11017.8,5821.93 h60
  text "PER" at 11217.8,5711.8 h60
  text "IPC-D-275 CLASS 2 LEVEL C" at 11437.8,5711.8 h60
  text "MIL, HOLES" at 12926.03,5611.32 h60
  text "+/-" at 12533.57,5602.74 h60
  text "+/-" at 13387.57,5602.74 h60
  text "REGISTRATION TOLERANCES:" at 11017.8,5601.67 h60
  text "METAL" at 12217.57,5601.67 h60
  text "5" at 12793.77,5601.67 h60
  text "3" at 13626.77,5601.67 h60
  text "MIL" at 13743.03,5601.67 h60
  text "HOLE SIZE TOLERANCE (UNLESS OTHERWISE SPECIFIED):" at 11017.8,5503.36 h60
  text "+/-" at 13387.57,5500.48 h60
  text "3" at 13626.77,5499.42 h60
  text "MIL" at 13743.03,5499.42 h60
  text "MATERIAL:" at 10943.03,5361.77 h60
  text "FR-4 High Tg" at 11929.47,5233.25 h60
  text "X" at 12671.57,5228.25 h60
  text "REFER STACK-UP" at 13172.42,5227.66 h55
  text "FR-408" at 11364.03,5220.74 h60
  text "OTHER" at 12852.03,5220.74 h60
  text "X" at 12842.57,5080.26 h60
  text "62 MIL (1.6mm) +/-10%" at 11684.13,5077.71 h60
  text "59 MIL +/-10%" at 13264.57,5071.25 h45
  text "THICKNESS:" at 11017.8,5069.49 h60
  text "OTHER" at 12969.03,5069.49 h60
  text "TOLERANCE:" at 11017.8,4931.18 h60
  text "X" at 11866.03,4931.18 h60
  text "ANSI IPC-6012 TYPE 3 CLASS 2" at 12044.04,4931.18 h60
  text "OTHER +/-" at 12044.03,4786.99 h60
  text "BOW & TWIST:" at 11017.8,4641.8 h60
  text "X" at 11866.03,4641.8 h60
  text "ANSI IPC-6012 TYPE 3 CLASS 2" at 12044.04,4641.8 h60
  text "B" at -806.93,4497.75 h70
  text "B" at 13993.07,4497.75 h70
  text "OTHER +/-" at 12044.03,4495.1 h60
  text "DRILLING:" at 10943.03,4364.48 h60
  text "NC_DRILL FILES" at 12704.03,4259.29 h60
  text "REFERENCE:" at 11017.8,4255.36 h60
  text "AS SHOWN" at 11853.03,4255.36 h60
  text "X" at 12576.03,4255.36 h60
  text "X" at 11675.03,4255.26 h60
  text "OTHER" at 13002.03,4113.1 h60
  text "PTH COPPER THICKNESS:" at 11017.47,4109.58 h60
  text "X" at 12156.71,4109.58 h60
  text "20-30 um" at 12284.7,4109.58 h60
  text "NOTES:" at 3578.86,3994.57 h60
  text "BOARD FINISH:" at 10943.03,3961.98 h60
  text "SILKSCREEN:" at 11098.25,3851.85 h60
  text "X" at 12056.03,3851.85 h60
  text "TOP" at 12173.03,3851.85 h60
  text "X" at 12566.03,3851.85 h60
  text "BOTTOM" at 12684.03,3851.85 h60
  text "1. BOARD SHALL MEET THE REQUIREMENTS OF UL-796E WITH FLAMMABILITY RATING OF MINIMUM 94V-0. UL LOGO," at 3605.62,3848.74 h60
  text "MANUFACTURER'S IDENTIFICATION AND DATE CODE LETTER SHALL BE RENDERED IN SILKSCREEN." at 3712.35,3749.75 h60
  text "SILKSCREEN COLOR:" at 11098.25,3696.66 h60
  text "X" at 12055.03,3696.66 h60
  text "WHITE" at 12173.03,3696.66 h60
  text "OTHER" at 12684.03,3696.66 h60
  text "2. VENDOR MAY ADJUST SOLDERMASK WHEREVER SOLDERMASK PADS ARE THE SAME SIZE (1:1) AS PER THE MANUFACTURING CAPABILITIES" at 3598.63,3623.96 h60
  text "GREEN" at 12304.03,3553.22 h60
  text "X" at 12778.03,3553.22 h60
  text "OTHER" at 12922.03,3553.22 h60
  text "RED" at 13294.57,3553.22 h60
  text "SOLDER RESIST COLOR:" at 11098.25,3546.35 h60
  text "AND ALL OTHER SOLDER MASK PADS SHALL NOT BE MODIFIED, PROVIDED NO ADJACENT COPPER IS EXPOSED AND NO CONFLICT IS PRODUCED" at 3705.36,3524.97 h60
  text "WITH ANY STATED \"VIA TENTING/COVERING\" REQUIREMENTS." at 3705.36,3431.68 h60
  text "MATTE" at 12304.03,3398.96 h60
  text "SEMI-GLOSS" at 12921.57,3398.32 h60
  text "X" at 12777.63,3396.27 h60
  text "3. MANUFACTURER'S IDENTIFICATION,DATECODE LETTER SHALL BE SILKSCREENED ON SOLDER SIDE OF THE BOARD." at 3602.31,3313.58 h60
  text "IMMERSION GOLD (ENIG)" at 12004.03,3226.19 h60
  text "ENEPIG" at 13341.57,3218.97 h60
  text "SURFACE FINISH:" at 10943.03,3217.97 h60
  text "4. TRACE WIDTH SHOULD BE ACCURATELY ETCHED. MAX TOLERANCE +/- 1 MIL." at 3597.35,3177.25 h60
  text "IMM. SILVER" at 13118.96,3090.33 h60
  text "IMM. TIN/SILVER OR EQUIV" at 11272.57,3080.66 h60
  text "X" at 12526.45,3077.97 h60
  text "OTHER" at 12704.03,3076.72 h60
  text "5. LAYER TO LAYER REGISTRATION SHALL BE WITHIN +/-2 MIL." at 3604.41,3053.14 h60
  text "6. REFER IMPEDANCE TABLE FOR IMPEDANCE CONTROL TRACES ON LAYER 1, 3, 6 & 8." at 3595.44,2932.27 h60
  text "ARRAY/PANEL:" at 10943.03,2921.34 h60
  text "CUT AND TRIM PER M1 BOARD OUTLINE" at 12004.03,2913.12 h60
  text "7. FOR ACCURACY OF THE ANTENNA DIMENSION, NEED TO BE MEASURE THE  ANTENNA DIMENSIONS ON ONE BOARD" at 3593.25,2780.51 h60
  text "X" at 11825.32,2778.38 h60
  text "N.C. ROUTE" at 12004.03,2777.15 h60
  text "V. SCORE" at 12870.03,2777.15 h60
  text "8. ALL VIAS ARE TENTED ON BOTH SIDES UNLESS OTHERWISE SOLDER MASK OPENED IN GERBER." at 3586.83,2667.83 h60
  text "CERTIFICATION:" at 10943.03,2648.03 h60
  text "MATERIALS AND WORKMANSHIP FOR ALL PCBS" at 11668.03,2648.03 h60
  text "TO MEET OR EXCEED THE REQUIREMENTS OF:" at 11668.03,2553.96 h60
  text "9. VIA HOLE OFFSET SHALL BE WITHIN 1MILS OF ITS ORIGINAL LOCATION" at 3590.77,2552.22 h60
  text "10. 7 MIL VIA  SHOULD BE FILLED WITH CONDUCTIVE COPPER AND SURFACE SHOULD BE FLAT" at 3545.02,2460.48 h60
  text "X" at 11305.54,2425.33 h60
  text "ANSI IPC-A-600F CLASS ->" at 11433.53,2425.33 h60
  text "X" at 13081.54,2425.33 h60
  text "2" at 13191.53,2425.33 h60
  text "1" at 12876.53,2423.84 h60
  text "3" at 13545.53,2423.84 h60
  text "BGA AREA VIAS SHOULD BE CAPPED WITH COPPER PLATING TO ENSURE FLAT SURFACE" at 3714.87,2357.34 h60
  text "X" at 12117.54,2277.65 h60
  text "RoHS" at 12245.53,2277.65 h60
  text "OTHER" at 12889.93,2277.65 h60
  text "PER ORDER" at 13286.99,2277.65 h60
  text "FLATNESS TOLERANCE FOR VIA ON PADS: +0.000 /- 0.001 INCHES ON BOTH SIDES." at 3713.13,2255.27 h60
  text "ALL BOARDS MUST MEET OR EXCEED UL94-V0 REQUIREMENTS." at 10970.57,2123.82 h60
  text "C" at -806.93,2122.75 h70
  text "C" at 13993.07,2122.75 h70
  text "PCB MUST BEAR THE UL94V-0 UL REGISTERED MATERIAL ID NUMBER" at 10970.57,2007.76 h60
  text "ADDITIONAL REQUIREMENTS:" at 10943.03,1838.33 h60
  text "MICROSECTION:" at 11017.8,1731.21 h60
  text "YES" at 11923.53,1731.21 h60
  text "REQUIRED" at 12785.03,1586.87 h60
  text "BARE BOARD ELEC. TEST:" at 11017.8,1584.02 h60
  text "NONE" at 12323.53,1584.02 h60
  text "X" at 12667.03,1584.02 h60
  text "PER ORDER" at 13377.03,1584.02 h60
  text "XX MIL VIAS REQUIRE NON-CONDUCTIVE FILL AND PLANARIZE" at 11201.57,1438.25 h59
  text "XX MIL VIAS REQUIRE CONDUCTIVE FILL AND PLANARIZE" at 11192.57,1279.25 h60
  text "OUTER XX MIL TRACES REQUIRE 50 OHM SINGLE-ENDED IMPEDANCE" at 11187.71,1136.35 h58
  text "LAYER 1 & 6 (INNER LAYERS) XX MIL WIDE, XX MIL SPACE / TRACES REQUIRE 100 OHM DIFFERENTIAL IMPEDANCE" at 11226.57,886.25 h60
  text "PROJECT TITLE:" at 10953.07,261.75 h45
  text ".PRJ_Title" at 11003.07,128.43 h70
  text "DESIGNED FOR:" at 10953.07,-39.25 h45
  text ".PRJ_Customer" at 11003.07,-179.25 h70
  text "D" at -806.93,-247.25 h70
  text "D" at 13993.07,-247.25 h70
  text "FILE NAME:" at 10953.07,-339.25 h45
  text ".PCB_File_Name_No_Path" at 11003.07,-459.25 h70
  text "Texas Instruments (TI) and/or its licensors do not warrant the accuracy or completeness of this specification" at 5983.57,-621.09 h45
  text "ENGINEER:" at 10953.07,-629.25 h45
  text "LAYOUT BY:" at 12458.07,-629.25 h45
  text "or any information contained therein. TI and/or its licensors do not warrant that this design will meet" at 5938.58,-733.75 h45
  text ".PRJ_Engineer" at 11003.07,-784.24 h70
  text ".PCB_Layout" at 12508.57,-784.24 h70
  text "the specifications, will be suitable for your application or fit for any particular purpose, or will operate in" at 5938.58,-846.42 h45
  text ".Layer_Name" at 183.98,-874.87 h60
  text "ALTIUM DESIGNER VERSION:" at 12458.07,-939.25 h45
  text "an implementation. TI and/or its licensors do not warrant that the design is production worthy. You should" at 5938.58,-959.08 h45
  text "completely validate and test your design implementation to confirm the system functionality for your application." at 5983.57,-1071.75 h45
  text ".print_Scale" at 11003.07,-1072.57 h70
  text ".Application_BuildNumber" at 12508.57,-1072.57 h70
  text "1" at 349.4,-1279.25 h70
  text "2" at 2845.07,-1279.25 h70
  text "3" at 5334.41,-1279.25 h70
  text "4" at 7841.08,-1279.25 h70
  text "5" at 10340.07,-1279.25 h70
  text "6" at 12694.25,-1289.6 h70
M11 Gerber Information:
  lines w10: -682.43,-945.91 5917.57,-945.91 ; -682.43,-742.58 5919.57,-742.58 ; -682.43,-539.25 -682.43,-1149.25 3322.57,-1149.25 5919.57,-1149.25 5919.57,-539.25 -681.93,-539.25 -681.93,-1149.25 893.57,-1149.25 ; 1782.57,-1149.25 1782.57,-539.25 ; 3049.57,-742.58 3049.57,-539.25 ; 3889.57,-742.58 3889.57,-539.25 ; 4511.57,-1155.75 4511.57,-952.91
  text "ALL ARTWORK VIEWED FROM TOP SIDE" at -618.93,-671.41 h60
  text "BOARD #:" at 1857.57,-671.41 h60
  text ".PRJ_Number" at 2403.07,-671.41 h60
  text "REV:" at 3247.57,-671.41 h60
  text ".PCB_Rev" at 3539.07,-671.41 h60
  text "SVN REV:" at 4085.57,-671.41 h60
  text ".VersionControl_RevNumber" at 4591.57,-671.41 h60
  text "LAYER NAME =" at -618.93,-874.24 h60
  text "TID #:" at 1857.57,-874.75 h60
  text ".TID" at 2403.07,-874.75 h60
  text "PLOT NAME =" at -618.93,-1080.08 h60
  text ".plot_File_Name" at 186.57,-1080.08 h60
  text "GENERATED    :" at 1859.57,-1080.08 h60
  text ".Print_Date" at 2729.07,-1080.08 h60
  text ".Print_Time" at 3458.07,-1080.08 h60
  text "TEXAS INSTRUMENTS" at 4722.57,-1080.08 h60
